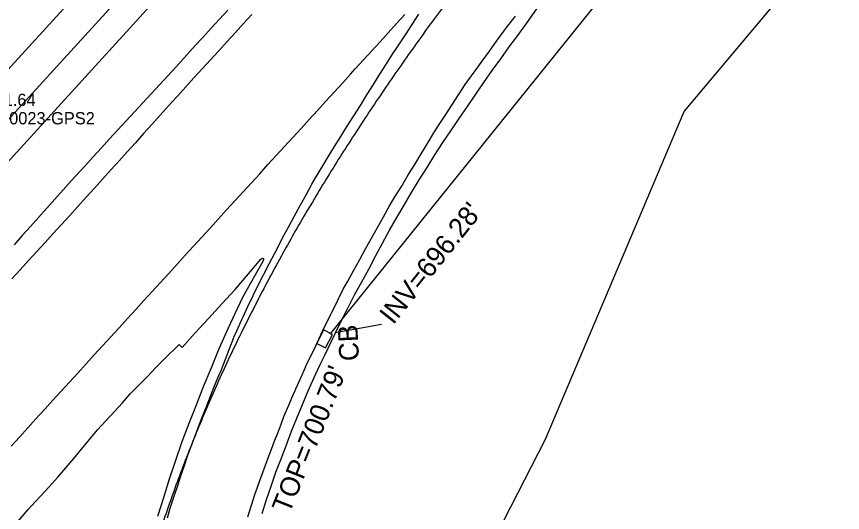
# Model space of a CAD drawing. Extents: x 1806071 to 1809844, y 912722 to 917035.
# Drawn here: x 1807362.2 to 1807530.6, y 914046.6 to 914147.7 of the extents above; entities that cross this region are included whole.
import ezdxf

# ---------------------------------------------------------------- set-up
doc = ezdxf.new("R2010")
doc.units = 0
for name, color, linetype in [('CTL GPS Vertical Cogo Comment', 7, 'Continuous'), ('CTL GPS Vertical Cogo Elevation', 7, 'Continuous'), ('Exist Guardrail Cable Guide Rail', 7, 'Continuous'), ('Exist Horizontal Alignment', 7, 'Continuous'), ('Exist Roads Curbs', 7, 'Continuous'), ('Exist Roads EOP', 7, 'Continuous'), ('Exist Roads EOT', 7, 'Continuous'), ('Exist Structure Minor Catch Basin', 7, 'Continuous'), ('Exist Structure Minor Catch Basin Text', 7, 'Continuous'), ('Exist Structure Minor Catch Basin Top Elevation', 7, 'Continuous'), ('Exist Structure Minor Pipes RCP 15 Inch', 7, 'Continuous'), ('Exist Structure Minor Pipes RCP 15 Inch Invert', 7, 'Continuous'), ('Exist Structure Minor Pipes RCP 24 Inch', 7, 'Continuous'), ('Exist Vegetation Woods Line', 7, 'Continuous')]:
    doc.layers.add(name, color=color, linetype=linetype)

msp = doc.modelspace()

# ---------------------------------------------------------------- linework, layer by layer
at = {"layer": 'Exist Guardrail Cable Guide Rail'}
msp.add_lwpolyline([(1807036.39, 913762.23), (1807072.19, 913801.95), (1807107.96, 913840.99), (1807141.41, 913877.77), (1807177.33, 913917.12), (1807208.48, 913951.28), (1807242.54, 913988.57), (1807278.56, 914027.99), (1807303.96, 914056.09), (1807333.75, 914088.73), (1807369.98, 914128.47), (1807402.65, 914164.36), (1807436.63, 914201.71), (1807469.41, 914237.65), (1807504.53, 914276.04), (1807531.63, 914306.03), (1807569.88, 914348.1), (1807608.39, 914390.29), (1807638.77, 914423.86), (1807675.81, 914465.75)], dxfattribs=at)
at = {"layer": 'Exist Horizontal Alignment'}
msp.add_line((1806073.69, 912724.84), (1809374.2, 916346.52), dxfattribs=at)
msp.add_arc((1806875.73, 914308.35), 954.93, 296.15643, 355.38963, dxfattribs=at)
for points in [[(1807524.97, 914238.66), (1807521.33, 914234.66), (1807517.69, 914230.66), (1807514.05, 914226.66), (1807510.42, 914222.66), (1807506.8, 914218.65), (1807503.18, 914214.63), (1807499.58, 914210.6), (1807495.99, 914206.56), (1807492.41, 914202.51), (1807488.85, 914198.44), (1807485.3, 914194.36), (1807481.78, 914190.26), (1807478.28, 914186.15), (1807474.8, 914182.01), (1807471.34, 914177.85), (1807467.91, 914173.68), (1807464.51, 914169.47), (1807461.15, 914165.24), (1807457.81, 914160.99), (1807454.51, 914156.71), (1807451.25, 914152.4), (1807448.03, 914148.06), (1807444.84, 914143.69), (1807441.71, 914139.29), (1807438.61, 914134.85), (1807435.57, 914130.39), (1807432.58, 914125.89), (1807429.64, 914121.35), (1807426.75, 914116.78), (1807423.93, 914112.17), (1807421.16, 914107.53), (1807418.45, 914102.85), (1807415.82, 914098.13), (1807413.24, 914093.38), (1807410.74, 914088.58), (1807408.31, 914083.76), (1807405.96, 914078.89), (1807403.69, 914073.99), (1807401.49, 914069.04), (1807399.39, 914064.07), (1807397.36, 914059.06), (1807395.43, 914054.01), (1807393.59, 914048.93), (1807391.84, 914043.81), (1807390.19, 914038.66), (1807388.65, 914033.48), (1807387.2, 914028.27), (1807385.87, 914023.04), (1807384.64, 914017.77), (1807383.52, 914012.48), (1807382.52, 914007.17), (1807381.64, 914001.84), (1807380.87, 913996.49), (1807380.23, 913991.12), (1807379.72, 913985.74), (1807379.33, 913980.35), (1807379.08, 913974.95), (1807378.96, 913969.55), (1807378.97, 913964.14), (1807379.13, 913958.74), (1807379.42, 913953.34), (1807379.85, 913947.95), (1807380.43, 913942.58), (1807381.16, 913937.22), (1807382.04, 913931.89), (1807383.06, 913926.58), (1807384.24, 913921.31), (1807385.57, 913916.07), (1807387.05, 913910.87), (1807388.69, 913905.72), (1807390.48, 913900.62), (1807392.43, 913895.58), (1807394.54, 913890.6), (1807396.8, 913885.69)], [(1807240.45, 914063.04), (1807242.27, 914065.04), (1807244.1, 914067.04), (1807245.92, 914069.04), (1807247.74, 914071.03), (1807249.56, 914073.03), (1807251.38, 914075.03), (1807253.19, 914077.03), (1807255.01, 914079.03), (1807256.83, 914081.03), (1807258.65, 914083.03), (1807260.47, 914085.03), (1807262.29, 914087.03), (1807264.1, 914089.03), (1807265.92, 914091.03), (1807267.73, 914093.03), (1807269.55, 914095.04), (1807271.36, 914097.04), (1807273.17, 914099.05), (1807274.99, 914101.05), (1807276.8, 914103.06), (1807278.61, 914105.06), (1807280.41, 914107.07), (1807282.22, 914109.08), (1807284.03, 914111.09), (1807285.83, 914113.1), (1807287.64, 914115.12), (1807289.44, 914117.13), (1807291.24, 914119.15), (1807293.04, 914121.16), (1807294.84, 914123.18), (1807296.64, 914125.2), (1807298.43, 914127.22), (1807300.22, 914129.24), (1807302.02, 914131.26), (1807303.81, 914133.29), (1807305.59, 914135.32), (1807307.38, 914137.34), (1807309.16, 914139.37), (1807310.95, 914141.41), (1807312.73, 914143.44), (1807314.51, 914145.47), (1807316.28, 914147.51), (1807318.06, 914149.55), (1807319.83, 914151.59), (1807321.6, 914153.63), (1807323.36, 914155.68), (1807325.13, 914157.73), (1807326.89, 914159.78), (1807328.65, 914161.83), (1807330.41, 914163.88), (1807332.16, 914165.94), (1807333.91, 914167.99), (1807335.66, 914170.05), (1807337.41, 914172.12), (1807339.15, 914174.18), (1807340.89, 914176.25), (1807342.63, 914178.32), (1807344.37, 914180.39), (1807346.1, 914182.47), (1807347.83, 914184.55), (1807349.55, 914186.63), (1807351.27, 914188.71), (1807352.99, 914190.79), (1807354.71, 914192.88), (1807356.42, 914194.97), (1807358.13, 914197.07), (1807359.83, 914199.17), (1807361.54, 914201.27), (1807363.23, 914203.37), (1807364.93, 914205.47), (1807366.62, 914207.58), (1807368.3, 914209.7), (1807369.99, 914211.81), (1807371.67, 914213.93)]]:
    msp.add_spline(points, degree=3, dxfattribs=at)
at = {"layer": 'Exist Roads Curbs'}
for points in [[(1807412.27, 914046.36), (1807413.17, 914049.22), (1807414.12, 914051.95), (1807415.12, 914054.77), (1807416.15, 914057.54), (1807417.25, 914060.33), (1807418.31, 914063.15), (1807419.4, 914065.83), (1807420.54, 914068.6), (1807421.68, 914071.35), (1807422.89, 914074.09), (1807424.1, 914076.73), (1807425.02, 914078.5), (1807427.2, 914083.04), (1807428.48, 914085.68), (1807429.85, 914088.38), (1807431.14, 914090.93), (1807432.59, 914093.56), (1807434.03, 914096.19), (1807435.44, 914098.83), (1807436.84, 914101.49), (1807438.27, 914104.12), (1807439.76, 914106.72), (1807441.23, 914109.23), (1807442.78, 914111.8), (1807444.33, 914114.36), (1807445.91, 914116.92), (1807447.53, 914119.44), (1807449.12, 914121.99), (1807450.76, 914124.39), (1807452.44, 914126.88), (1807454.18, 914129.32), (1807455.86, 914131.81), (1807457.47, 914134.18), (1807459.18, 914136.64), (1807460.94, 914139.07), (1807462.68, 914141.51), (1807464.41, 914143.8), (1807466.18, 914146.21), (1807469.09, 914150.35)], [(1807395.97, 914080.22), (1807398.66, 914083.18), (1807401.35, 914086.13), (1807404.06, 914089.08), (1807406.78, 914092.02), (1807409.49, 914095.21), (1807412.02, 914098.18), (1807412.2, 914098.33), (1807412.39, 914098.38), (1807412.54, 914098.34), (1807412.6, 914098.2), (1807412.47, 914097.89), (1807410.73, 914094.77), (1807408.35, 914090.5), (1807406.63, 914086.92), (1807404.93, 914083.27), (1807403.35, 914079.57), (1807401.83, 914075.87), (1807400.28, 914072.17), (1807398.82, 914068.45), (1807397.36, 914064.72), (1807395.95, 914060.95), (1807394.66, 914057.17), (1807393.34, 914053.36), (1807392.15, 914049.54), (1807390.93, 914045.74)]]:
    msp.add_lwpolyline(points, dxfattribs=at)
at = {"layer": 'Exist Roads EOP'}
for points in [[(1807405.28, 914148.96), (1807403.6, 914147.11), (1807401.92, 914145.26), (1807400.23, 914143.41), (1807399.81, 914142.95), (1807398.12, 914141.11), (1807396.43, 914139.27), (1807394.74, 914137.43), (1807393.05, 914135.59), (1807391.35, 914133.75), (1807389.66, 914131.91), (1807387.97, 914130.07), (1807386.28, 914128.23), (1807384.59, 914126.39), (1807382.89, 914124.55), (1807381.2, 914122.71), (1807379.51, 914120.87), (1807377.82, 914119.03), (1807376.12, 914117.19), (1807375.06, 914116.03), (1807373.39, 914114.17), (1807371.73, 914112.31), (1807370.06, 914110.45), (1807368.39, 914108.59), (1807366.72, 914106.73), (1807365.05, 914104.87), (1807363.38, 914103.01), (1807361.71, 914101.15)], [(1807409.36, 914045.67), (1807410.12, 914048.05), (1807410.88, 914050.44), (1807410.98, 914050.75), (1807411.83, 914053.1), (1807412.69, 914055.45), (1807413.31, 914057.17), (1807414.21, 914059.51), (1807415.11, 914061.84), (1807415.2, 914062.07), (1807416.09, 914064.4), (1807416.75, 914066.16), (1807417.74, 914068.46), (1807418.72, 914070.75), (1807418.93, 914071.24), (1807419.16, 914071.76), (1807420.16, 914074.05), (1807421.17, 914076.34), (1807421.3, 914076.63), (1807422.4, 914078.87), (1807423.21, 914080.55), (1807423.44, 914081.04), (1807424.28, 914082.81), (1807425.04, 914084.43), (1807426.16, 914086.66), (1807427.28, 914088.9), (1807427.52, 914089.36), (1807427.75, 914089.83), (1807428.84, 914092.08), (1807429.76, 914093.75), (1807430.98, 914095.93), (1807432.19, 914098.12), (1807433.4, 914100.31), (1807434.62, 914102.49), (1807435.83, 914104.68), (1807437.05, 914106.86), (1807438.26, 914109.05), (1807439.51, 914111.11), (1807440.81, 914113.25), (1807442.1, 914115.39), (1807443.4, 914117.52), (1807444.69, 914119.66), (1807445.99, 914121.8), (1807447.29, 914123.94), (1807448.26, 914125.43), (1807449.62, 914127.52), (1807450.99, 914129.62), (1807452.35, 914131.71), (1807453.72, 914133.81), (1807454.24, 914134.54), (1807455.71, 914136.57), (1807457.17, 914138.59), (1807458.63, 914140.62), (1807460.09, 914142.65), (1807461.55, 914144.68), (1807462.41, 914145.76), (1807463.97, 914147.71)], [(1807360.88, 914043.07), (1807362.57, 914044.91), (1807362.93, 914045.3), (1807364.61, 914047.16), (1807366.04, 914048.73), (1807367.2, 914049.99), (1807368.88, 914051.83), (1807370.57, 914053.68), (1807370.66, 914053.77), (1807372.27, 914055.69), (1807373.88, 914057.6), (1807375.49, 914059.51), (1807377.1, 914061.42), (1807378.76, 914063.39), (1807380.44, 914065.24), (1807382.12, 914067.09), (1807383.8, 914068.95), (1807385.42, 914070.73), (1807387.16, 914072.52), (1807388.9, 914074.32), (1807390.63, 914076.12), (1807392.37, 914077.91), (1807395.35, 914080.8), (1807395.97, 914080.22)]]:
    msp.add_lwpolyline(points, dxfattribs=at)
at = {"layer": 'Exist Roads EOT'}
for points in [[(1807361.14, 914060.1), (1807362.82, 914061.95), (1807364.5, 914063.8), (1807366.18, 914065.65), (1807367.86, 914067.5), (1807367.97, 914067.62), (1807369.65, 914069.46), (1807371.34, 914071.31), (1807373.02, 914073.15), (1807374.71, 914075), (1807376.4, 914076.85), (1807378.08, 914078.69), (1807379.77, 914080.54), (1807381.45, 914082.39), (1807383.14, 914084.23), (1807384.82, 914086.08), (1807386.51, 914087.93), (1807388.19, 914089.77), (1807389.88, 914091.62), (1807391.57, 914093.46), (1807393.25, 914095.31), (1807394.94, 914097.16), (1807396.62, 914099), (1807398.31, 914100.85), (1807399.99, 914102.7), (1807401.68, 914104.54), (1807403.36, 914106.39), (1807405.05, 914108.24), (1807406.74, 914110.08), (1807408.42, 914111.93), (1807410.11, 914113.77), (1807411.79, 914115.62), (1807413.48, 914117.47), (1807415.16, 914119.31), (1807416.85, 914121.16), (1807418.53, 914123.01), (1807420.22, 914124.85), (1807421.9, 914126.7), (1807423.59, 914128.54), (1807425.28, 914130.39), (1807426.96, 914132.24), (1807428.65, 914134.08), (1807430.33, 914135.93), (1807431.28, 914136.97), (1807432.96, 914138.81), (1807434.65, 914140.66), (1807436.33, 914142.51), (1807438.01, 914144.36), (1807439.7, 914146.21), (1807441.38, 914148.05)], [(1807410.2, 914148.07), (1807408.52, 914146.23), (1807406.83, 914144.38), (1807405.14, 914142.54), (1807403.46, 914140.69), (1807401.77, 914138.85), (1807400.09, 914137), (1807398.4, 914135.15), (1807396.71, 914133.31), (1807395.03, 914131.46), (1807394.82, 914131.24), (1807393.15, 914129.38), (1807391.48, 914127.53), (1807389.8, 914125.67), (1807388.13, 914123.81), (1807386.45, 914121.95), (1807384.78, 914120.1), (1807383.11, 914118.24), (1807381.43, 914116.38), (1807379.76, 914114.53), (1807378.09, 914112.67), (1807376.41, 914110.81), (1807374.74, 914108.96), (1807373.09, 914107.13), (1807371.4, 914105.28), (1807369.71, 914103.44), (1807368.03, 914101.6), (1807366.34, 914099.75), (1807364.65, 914097.91), (1807362.96, 914096.06), (1807361.27, 914094.22)], [(1807406.54, 914082.29), (1807407.13, 914083.62), (1807408.15, 914085.9), (1807408.33, 914086.29), (1807409.41, 914088.55), (1807410.48, 914090.8), (1807411.43, 914092.79), (1807412.57, 914095.01), (1807413.72, 914097.23), (1807414.86, 914099.46), (1807416.01, 914101.68), (1807416.45, 914102.53), (1807417.65, 914104.73), (1807418.85, 914106.92), (1807420.05, 914109.11), (1807421.25, 914111.31), (1807422.45, 914113.5), (1807423.16, 914114.79), (1807424.47, 914116.92), (1807425.78, 914119.05), (1807427.08, 914121.18), (1807428.33, 914123.21), (1807429.66, 914125.32), (1807430.99, 914127.44), (1807432.32, 914129.55), (1807433.66, 914131.67), (1807434.99, 914133.78), (1807436.32, 914135.9), (1807437.66, 914138.01), (1807438.77, 914139.78), (1807440.15, 914141.87), (1807441.52, 914143.96), (1807442.9, 914146.04), (1807444.27, 914148.13)], [(1807393, 914045.49), (1807393.57, 914047.48), (1807394.37, 914049.93), (1807395.15, 914052.31), (1807395.65, 914053.82), (1807396.45, 914056.18), (1807397.1, 914058.07), (1807397.97, 914060.41), (1807398.83, 914062.76), (1807398.98, 914063.15), (1807399.89, 914065.48), (1807400.8, 914067.81), (1807400.86, 914067.96), (1807401.78, 914070.29), (1807402.47, 914072.03), (1807403.43, 914074.34), (1807403.91, 914075.49), (1807404.81, 914077.82), (1807405.71, 914080.15), (1807406.52, 914082.26)]]:
    msp.add_lwpolyline(points, dxfattribs=at)
at = {"layer": 'Exist Structure Minor Catch Basin'}
msp.add_lwpolyline([(1807424.81, 914083.77), (1807423.44, 914081.03), (1807425.24, 914080.12), (1807426.62, 914082.86)], close=True, dxfattribs=at)
at = {"layer": 'Exist Structure Minor Pipes RCP 15 Inch'}
msp.add_line((1807426.13, 914082.91), (1807623.11, 914327.12), dxfattribs=at)
at = {"layer": 'Exist Structure Minor Pipes RCP 15 Inch Invert'}
msp.add_line((1807427.16, 914083.24), (1807436.61, 914084.96), dxfattribs=at)
at = {"layer": 'Exist Structure Minor Pipes RCP 24 Inch'}
msp.add_line((1807298.31, 914058.62), (1807569.06, 914354.69), dxfattribs=at)
at = {"layer": 'Exist Vegetation Woods Line'}
msp.add_lwpolyline([(1807453.05, 914028.36), (1807470.08, 914061.5), (1807498.37, 914128.33), (1807525.94, 914161.18), (1807561.14, 914200.23), (1807596.23, 914239.09), (1807629.09, 914277.74), (1807650.72, 914303.3), (1807690.07, 914341.96), (1807725.62, 914371.62), (1807753.24, 914396.28)], dxfattribs=at)

# ---------------------------------------------------------------- texts
at = {"layer": 'CTL GPS Vertical Cogo Comment'}
msp.add_text('78-0023-GPS2', height=2.5, dxfattribs=at).set_placement((1807355.88, 914125.68))
at = {"layer": 'CTL GPS Vertical Cogo Elevation'}
msp.add_text('701.64', height=2.5, dxfattribs=at).set_placement((1807355.88, 914129.43))
at = {"layer": 'Exist Structure Minor Catch Basin Text'}
msp.add_text('CB', height=4, rotation=92.8422, dxfattribs=at).set_placement((1807432.06, 914077.53))
at = {"layer": 'Exist Structure Minor Catch Basin Top Elevation'}
msp.add_text("TOP=700.79'", height=4, rotation=68.1245, dxfattribs=at).set_placement((1807417.87, 914046.17))
at = {"layer": 'Exist Structure Minor Pipes RCP 15 Inch Invert'}
msp.add_text("INV=696.28'", height=4, rotation=51.4951, dxfattribs=at).set_placement((1807439.02, 914084.69))

doc.saveas('drawing.dxf')
